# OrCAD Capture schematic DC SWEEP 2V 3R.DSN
size A
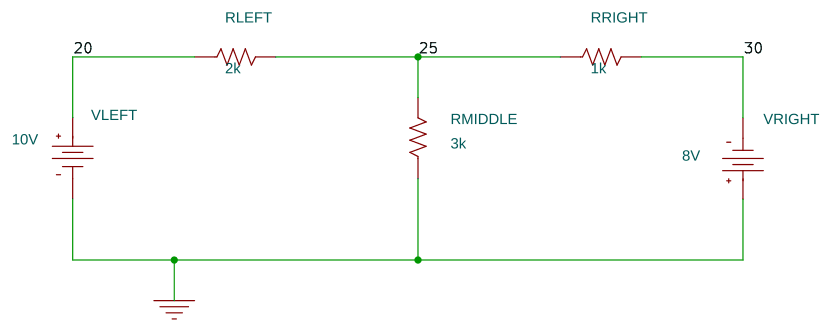
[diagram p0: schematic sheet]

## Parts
RLEFT  2k  [AX/RC05]
RMIDDLE  3k  [AX/RC05]
RRIGHT  1k  [AX/RC05]
VLEFT  VDC
VRIGHT  VDC

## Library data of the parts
RLEFT RMIDDLE RRIGHT = R
VLEFT = VDC: DC: 10V
VRIGHT = VDC: DC: 8V

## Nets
0: RMIDDLE.1 VLEFT.1(-) VRIGHT.0(+)
20: RLEFT.1 VLEFT.0(+)
25: RLEFT.2 RMIDDLE.2 RRIGHT.1
30: RRIGHT.2 VRIGHT.1(-)
